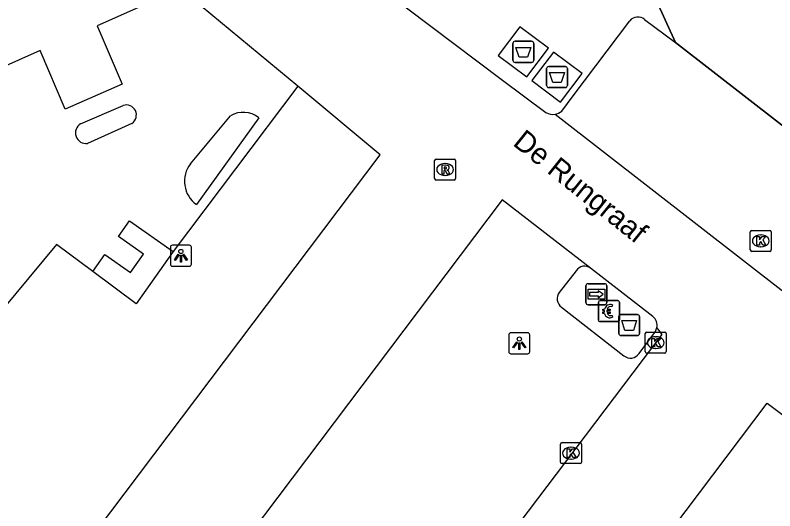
# Model space of a CAD drawing. Extents: x 160664 to 161506, y 382245 to 383288.
# Drawn here: x 161006.23 to 161042.33, y 382872.87 to 382896.43 of the extents above; entities that cross this region are included whole.
import ezdxf

# ---------------------------------------------------------------- set-up
doc = ezdxf.new("R2010")
doc.units = 0
for name, color, linetype in [('IMGEO_Afval_apart_plaats', 7, 'Continuous'), ('IMGEO_Afvalbak', 7, 'Continuous'), ('IMGEO_Betaalautomaat', 7, 'Continuous'), ('IMGEO_Kolk', 7, 'Continuous'), ('IMGEO_Lichtpunt', 7, 'Continuous'), ('IMGEO_Muur', 7, 'Continuous'), ('IMGEO_Openbare_ruimte_label', 7, 'Continuous'), ('IMGEO_Pand', 7, 'Continuous'), ('IMGEO_Parkeervlak_open', 7, 'Continuous'), ('IMGEO_Rijbaan_lokaal_open', 7, 'Continuous'), ('IMGEO_Rioolput', 7, 'Continuous'), ('IMGEO_Voetpad_gesloten', 7, 'Continuous'), ('IMGEO_Voetpad_open', 7, 'Continuous'), ('IMGEO_Wegwijzer', 7, 'Continuous')]:
    doc.layers.add(name, color=color, linetype=linetype)

msp = doc.modelspace()

# ---------------------------------------------------------------- linework, layer by layer
at = {"layer": 'IMGEO_Afval_apart_plaats'}
for p, q in [((161029.884, 382894.283), (161029.884, 382895.083)), ((161029.884, 382895.083), (161029.884, 382894.283)), ((161029.984, 382895.183), (161030.774, 382895.183)), ((161030.774, 382895.183), (161029.984, 382895.183)), ((161030.874, 382895.083), (161030.874, 382894.283)), ((161030.874, 382894.283), (161030.874, 382895.083)), ((161030.774, 382894.183), (161029.984, 382894.183)), ((161029.984, 382894.183), (161030.774, 382894.183)), ((161031.486, 382893.086), (161031.486, 382893.886)), ((161031.486, 382893.886), (161031.486, 382893.086)), ((161031.586, 382893.986), (161032.376, 382893.986)), ((161032.376, 382893.986), (161031.586, 382893.986)), ((161032.476, 382893.886), (161032.476, 382893.086)), ((161032.476, 382893.086), (161032.476, 382893.886)), ((161032.376, 382892.986), (161031.586, 382892.986)), ((161031.586, 382892.986), (161032.376, 382892.986))]:
    msp.add_line(p, q, dxfattribs=at)
for points in [[(161030.027, 382894.897), (161030.731, 382894.897), (161030.582, 382894.427), (161030.176, 382894.427), (161030.027, 382894.897)], [(161031.629, 382893.7), (161032.333, 382893.7), (161032.184, 382893.23), (161031.778, 382893.23), (161031.629, 382893.7)]]:
    msp.add_lwpolyline(points, dxfattribs=at)
for centre, start, end in [((161029.984, 382895.083), 90, 180), ((161029.984, 382895.083), 90, 180), ((161030.774, 382895.083), 0, 90), ((161030.774, 382895.083), 360, 90), ((161029.984, 382894.283), 180, 270), ((161029.984, 382894.283), 180, 270), ((161030.774, 382894.283), 270, 0), ((161030.774, 382894.283), 270, 0), ((161031.586, 382893.886), 90, 180), ((161031.586, 382893.886), 90, 180), ((161032.376, 382893.886), 0, 90), ((161032.376, 382893.886), 360, 90), ((161031.586, 382893.086), 180, 270), ((161031.586, 382893.086), 180, 270), ((161032.376, 382893.086), 270, 0), ((161032.376, 382893.086), 270, 0)]:
    msp.add_arc(centre, 0.1, start, end, dxfattribs=at)
at = {"layer": 'IMGEO_Afvalbak'}
for p, q in [((161034.915, 382881.298), (161034.915, 382882.098)), ((161034.915, 382882.098), (161034.915, 382881.298)), ((161035.015, 382882.198), (161035.805, 382882.198)), ((161035.805, 382882.198), (161035.015, 382882.198)), ((161035.905, 382882.098), (161035.905, 382881.298)), ((161035.905, 382881.298), (161035.905, 382882.098)), ((161035.805, 382881.198), (161035.015, 382881.198)), ((161035.015, 382881.198), (161035.805, 382881.198))]:
    msp.add_line(p, q, dxfattribs=at)
msp.add_lwpolyline([(161035.058, 382881.912), (161035.762, 382881.912), (161035.613, 382881.442), (161035.207, 382881.442), (161035.058, 382881.912)], dxfattribs=at)
for centre, start, end in [((161035.015, 382882.098), 90, 180), ((161035.015, 382882.098), 90, 180), ((161035.805, 382882.098), 0, 90), ((161035.805, 382882.098), 360, 90), ((161035.015, 382881.298), 180, 270), ((161035.015, 382881.298), 180, 270), ((161035.805, 382881.298), 270, 0), ((161035.805, 382881.298), 270, 0)]:
    msp.add_arc(centre, 0.1, start, end, dxfattribs=at)
at = {"layer": 'IMGEO_Betaalautomaat'}
for p, q in [((161033.948, 382881.936), (161033.948, 382882.777)), ((161033.948, 382882.777), (161033.948, 382881.936)), ((161034.023, 382882.86), (161034.864, 382882.86)), ((161034.864, 382882.86), (161034.023, 382882.86)), ((161034.947, 382882.786), (161034.947, 382881.945)), ((161034.947, 382881.945), (161034.947, 382882.786)), ((161034.231, 382882.324), (161034.231, 382882.392)), ((161034.352, 382882.392), (161034.352, 382882.324)), ((161034.61, 382882.665), (161034.593, 382882.565)), ((161034.597, 382882.159), (161034.619, 382882.072)), ((161034.873, 382881.861), (161034.032, 382881.861)), ((161034.032, 382881.861), (161034.873, 382881.861))]:
    msp.add_line(p, q, dxfattribs=at)
for points in [[(161034.231, 382882.392), (161034.162, 382882.392), (161034.162, 382882.461), (161034.241, 382882.461)], [(161034.363, 382882.461), (161034.51, 382882.461), (161034.51, 382882.392), (161034.352, 382882.392)], [(161034.236, 382882.255), (161034.162, 382882.255), (161034.162, 382882.324), (161034.231, 382882.324)], [(161034.352, 382882.324), (161034.51, 382882.324), (161034.51, 382882.255), (161034.366, 382882.255)]]:
    msp.add_lwpolyline(points, dxfattribs=at)
for centre, radius, start, end in [((161034.026, 382882.783), 0.0779, 92.4484, 184.2845), ((161034.026, 382882.783), 0.0779, 92.4484, 184.2845), ((161034.87, 382882.783), 0.0779, 2.4484, 94.2845), ((161034.87, 382882.783), 0.0779, 2.4484, 94.2845), ((161034.524, 382882.385), 0.293, 73.014, 165.0139), ((161034.53, 382882.398), 0.179, 69.3236, 159.5683), ((161034.497, 382882.31), 0.267, 191.8096, 297.0389), ((161034.53, 382882.325), 0.179, 202.7625, 291.8693), ((161034.026, 382881.939), 0.0779, 182.4484, 274.2845), ((161034.026, 382881.939), 0.0779, 182.4484, 274.2845), ((161034.87, 382881.939), 0.0779, 272.4484, 4.2845), ((161034.87, 382881.939), 0.0779, 272.4484, 4.2845)]:
    msp.add_arc(centre, radius, start, end, dxfattribs=at)
at = {"layer": 'IMGEO_Kolk'}
for p, q in [((161041.162, 382885.274), (161041.162, 382886.126)), ((161041.237, 382886.2), (161042.089, 382886.2)), ((161041.65, 382885.98), (161041.675, 382885.98)), ((161042.163, 382886.126), (161042.163, 382885.274)), ((161041.673, 382885.42), (161041.648, 382885.42)), ((161042.089, 382885.2), (161041.237, 382885.2)), ((161036.173, 382880.438), (161036.173, 382881.29)), ((161036.248, 382881.364), (161037.1, 382881.364)), ((161037.174, 382881.29), (161037.174, 382880.438)), ((161036.661, 382881.144), (161036.686, 382881.144)), ((161036.684, 382880.584), (161036.659, 382880.584)), ((161037.1, 382880.364), (161036.248, 382880.364)), ((161032.144, 382875.186), (161032.144, 382876.038)), ((161032.219, 382876.112), (161033.071, 382876.112)), ((161032.632, 382875.892), (161032.657, 382875.892)), ((161033.145, 382876.038), (161033.145, 382875.186)), ((161032.655, 382875.332), (161032.63, 382875.332)), ((161033.071, 382875.112), (161032.219, 382875.112))]:
    msp.add_line(p, q, dxfattribs=at)
for points in [[(161041.162, 382885.274), (161041.162, 382886.126)], [(161041.237, 382886.2), (161042.089, 382886.2)], [(161042.163, 382886.126), (161042.163, 382885.274)], [(161041.483, 382885.9), (161041.606, 382885.9), (161041.606, 382885.749), (161041.736, 382885.9), (161041.9, 382885.9), (161041.754, 382885.749), (161041.907, 382885.5), (161041.755, 382885.5), (161041.67, 382885.664), (161041.606, 382885.597), (161041.606, 382885.5), (161041.483, 382885.5), (161041.483, 382885.9)], [(161042.089, 382885.2), (161041.237, 382885.2)], [(161036.173, 382880.438), (161036.173, 382881.29)], [(161036.248, 382881.364), (161037.1, 382881.364)], [(161037.174, 382881.29), (161037.174, 382880.438)], [(161036.494, 382881.064), (161036.617, 382881.064), (161036.617, 382880.913), (161036.747, 382881.064), (161036.911, 382881.064), (161036.765, 382880.913), (161036.918, 382880.664), (161036.766, 382880.664), (161036.681, 382880.828), (161036.617, 382880.761), (161036.617, 382880.664), (161036.494, 382880.664), (161036.494, 382881.064)], [(161037.1, 382880.364), (161036.248, 382880.364)], [(161032.144, 382875.186), (161032.144, 382876.038)], [(161032.219, 382876.112), (161033.071, 382876.112)], [(161033.145, 382876.038), (161033.145, 382875.186)], [(161032.465, 382875.812), (161032.588, 382875.812), (161032.588, 382875.661), (161032.718, 382875.812), (161032.882, 382875.812), (161032.736, 382875.661), (161032.889, 382875.412), (161032.737, 382875.412), (161032.652, 382875.576), (161032.588, 382875.509), (161032.588, 382875.412), (161032.465, 382875.412), (161032.465, 382875.812)], [(161033.071, 382875.112), (161032.219, 382875.112)]]:
    msp.add_lwpolyline(points, dxfattribs=at)
for centre, start, end in [((161041.239, 382886.124), 91.552, 178.448), ((161041.239, 382886.124), 91.552, 178.448), ((161042.087, 382886.124), 1.552, 88.448), ((161042.087, 382886.124), 1.552, 88.448), ((161041.239, 382885.276), 181.552, 268.448), ((161041.239, 382885.276), 181.552, 268.448), ((161042.087, 382885.276), 271.552, 358.448), ((161042.087, 382885.276), 271.552, 358.448), ((161036.25, 382881.288), 91.552, 178.448), ((161036.25, 382881.288), 91.552, 178.448), ((161037.098, 382881.288), 1.552, 88.448), ((161037.098, 382881.288), 1.552, 88.448), ((161036.25, 382880.44), 181.552, 268.448), ((161036.25, 382880.44), 181.552, 268.448), ((161037.098, 382880.44), 271.552, 358.448), ((161037.098, 382880.44), 271.552, 358.448), ((161032.221, 382876.036), 91.552, 178.448), ((161032.221, 382876.036), 91.552, 178.448), ((161033.069, 382876.036), 1.552, 88.448), ((161033.069, 382876.036), 1.552, 88.448), ((161032.221, 382875.188), 181.552, 268.448), ((161032.221, 382875.188), 181.552, 268.448), ((161033.069, 382875.188), 271.552, 358.448), ((161033.069, 382875.188), 271.552, 358.448)]:
    msp.add_arc(centre, 0.0765, start, end, dxfattribs=at)
for centre, major_axis, ratio, start_param, end_param in [((161041.649, 382885.7), (-0.387, 0.002), 0.722429, 4.712389, 7.853982), ((161041.674, 382885.7), (-0.39, 0.002), 0.717154, 1.570796, 4.712389), ((161036.66, 382880.864), (-0.387, 0.002), 0.722429, 4.712389, 7.853982), ((161036.685, 382880.864), (-0.39, 0.002), 0.717154, 1.570796, 4.712389), ((161032.631, 382875.612), (-0.387, 0.002), 0.722429, 4.712389, 7.853982), ((161032.656, 382875.612), (-0.39, 0.002), 0.717154, 1.570796, 4.712389)]:
    msp.add_ellipse(centre, major_axis=major_axis, ratio=ratio, start_param=start_param, end_param=end_param, dxfattribs=at)
at = {"layer": 'IMGEO_Lichtpunt'}
for p, q in [((161013.608, 382885.398), (161013.608, 382884.591)), ((161013.608, 382885.398), (161013.608, 382884.591)), ((161014.51, 382885.493), (161013.702, 382885.493)), ((161014.51, 382885.493), (161013.702, 382885.493)), ((161014.604, 382884.591), (161014.604, 382885.398)), ((161014.604, 382884.591), (161014.604, 382885.398)), ((161013.702, 382884.497), (161014.51, 382884.497)), ((161013.702, 382884.497), (161014.51, 382884.497)), ((161030.593, 382881.332), (161029.785, 382881.332)), ((161030.593, 382881.332), (161029.785, 382881.332)), ((161029.691, 382881.237), (161029.691, 382880.43)), ((161029.691, 382881.237), (161029.691, 382880.43)), ((161030.687, 382880.43), (161030.687, 382881.237)), ((161030.687, 382880.43), (161030.687, 382881.237)), ((161029.785, 382880.336), (161030.593, 382880.336)), ((161029.785, 382880.336), (161030.593, 382880.336))]:
    msp.add_line(p, q, dxfattribs=at)
for points in [[(161013.982, 382885.062), (161014.021, 382885.034), (161013.833, 382884.772), (161013.795, 382884.799), (161013.982, 382885.062)], [(161014.084, 382885.014), (161014.131, 382885.014), (161014.131, 382884.692), (161014.084, 382884.692), (161014.084, 382885.014)], [(161014.194, 382885.034), (161014.232, 382885.061), (161014.419, 382884.799), (161014.38, 382884.771), (161014.194, 382885.034)], [(161030.065, 382880.901), (161030.104, 382880.873), (161029.916, 382880.611), (161029.878, 382880.638), (161030.065, 382880.901)], [(161030.277, 382880.873), (161030.315, 382880.9), (161030.502, 382880.638), (161030.463, 382880.61), (161030.277, 382880.873)], [(161030.167, 382880.853), (161030.214, 382880.853), (161030.214, 382880.531), (161030.167, 382880.531), (161030.167, 382880.853)]]:
    msp.add_lwpolyline(points, dxfattribs=at)
for centre in [(161014.107, 382885.196), (161030.19, 382881.035)]:
    msp.add_circle(centre, 0.0994, dxfattribs=at)
for centre, start, end in [((161013.702, 382885.398), 90, 180), ((161013.702, 382885.398), 90, 180), ((161014.51, 382885.398), 0, 90), ((161014.51, 382885.398), 0, 90), ((161013.702, 382884.591), 180, 270), ((161013.702, 382884.591), 180, 270), ((161014.51, 382884.591), 270, 0), ((161014.51, 382884.591), 270, 360), ((161029.785, 382881.237), 90, 180), ((161029.785, 382881.237), 90, 180), ((161030.593, 382881.237), 0, 90), ((161030.593, 382881.237), 0, 90), ((161029.785, 382880.43), 180, 270), ((161029.785, 382880.43), 180, 270), ((161030.593, 382880.43), 270, 0), ((161030.593, 382880.43), 270, 360)]:
    msp.add_arc(centre, 0.0946, start, end, dxfattribs=at)
at = {"layer": 'IMGEO_Muur'}
for points in [[(161037.616, 382895.122), (161035.229, 382900.358)], [(161055.707, 382881.074), (161037.616, 382895.122)]]:
    msp.add_lwpolyline(points, dxfattribs=at)
at = {"layer": 'IMGEO_Pand'}
msp.add_lwpolyline([(161014.607, 382897.256), (161014.294, 382897.128), (161014.052, 382897.682), (161010.131, 382895.912), (161011.314, 382893.149), (161008.614, 382891.962), (161007.416, 382894.745), (161001.969, 382892.326)], dxfattribs=at)
at = {"layer": 'IMGEO_Parkeervlak_open'}
for points in [[(161037.616, 382895.122), (161055.707, 382881.074)], [(161013.737, 382885.191), (161011.983, 382882.707), (161009.918, 382884.242)], [(161032.897, 382884.273), (161032.088, 382883.243)], [(161032.196, 382882.556), (161035.156, 382880.239)], [(161035.877, 382880.352), (161036.656, 382881.396), (161036.728, 382881.578)]]:
    msp.add_lwpolyline(points, dxfattribs=at)
for centre, radius, start, end in [((161033.296, 382884.035), 0.465, 52.7846, 149.1864), ((161032.463, 382882.95), 0.476, 142.0313, 235.8369), ((161035.467, 382880.614), 0.487, 230.3779, 327.4368)]:
    msp.add_arc(centre, radius, start, end, dxfattribs=at)
at = {"layer": 'IMGEO_Rijbaan_lokaal_open'}
for points in [[(161021.072, 382900.069), (161021.429, 382899.354), (161029.397, 382893.332), (161031.451, 382891.801)], [(161019.667, 382893.047), (161014.607, 382897.256)], [(161009.04, 382847.522), (161000, 382856.514), (160999.119, 382857.39), (161000, 382858.557), (161023.576, 382889.795), (161019.667, 382893.047)], [(161019.667, 382893.047), (161013.737, 382885.191)], [(161009.339, 382891.266), (161011.367, 382892.137)], [(161014.562, 382889.368), (161016.46, 382891.642)], [(161017.809, 382891.547), (161014.848, 382887.425)], [(161031.89, 382891.715), (161051.844, 382876.215), (161052.657, 382877.184), (161052.932, 382876.971), (161053.162, 382877.241)], [(161011.779, 382891.285), (161009.674, 382890.329)], [(161033.577, 382884.405), (161029.375, 382887.651), (161006.741, 382857.643), (161014.674, 382851.774), (161036.973, 382881.256), (161036.728, 382881.578)], [(161009.918, 382884.242), (161010.488, 382885.049), (161011.711, 382884.193), (161012.331, 382885.071), (161011.148, 382885.907), (161011.672, 382886.65), (161013.737, 382885.191)], [(161009.918, 382884.242), (161008.193, 382885.524), (160999.832, 382875.47), (160993.888, 382867.215), (160990.918, 382863.091), (160990.417, 382861.086), (160992.626, 382856.489), (161001.149, 382847.95), (161005.762, 382843.842)], [(161036.539, 382882.101), (161033.577, 382884.405)], [(161041.959, 382877.99), (161050.071, 382871.893), (161026.197, 382840.33), (161018.147, 382846.412), (161041.959, 382877.99)]]:
    msp.add_lwpolyline(points, dxfattribs=at)
for centre, radius, start, end in [((161011.513, 382891.682), 0.478, 303.8506, 107.7633), ((161017.066, 382890.627), 1.183, 51.101, 120.8425), ((161031.785, 382892.341), 0.635, 238.2925, 279.5398), ((161009.604, 382890.833), 0.508, 121.4862, 277.8601), ((161015.642, 382888.534), 1.364, 142.3441, 234.403), ((161036.199, 382881.682), 0.539, 348.8379, 50.8995)]:
    msp.add_arc(centre, radius, start, end, dxfattribs=at)
at = {"layer": 'IMGEO_Rioolput'}
for p, q in [((161026.237, 382889.59), (161027.089, 382889.59)), ((161026.162, 382888.664), (161026.162, 382889.516)), ((161026.65, 382889.37), (161026.675, 382889.37)), ((161027.163, 382889.516), (161027.163, 382888.664)), ((161027.089, 382888.59), (161026.237, 382888.59)), ((161026.673, 382888.81), (161026.648, 382888.81))]:
    msp.add_line(p, q, dxfattribs=at)
for points in [[(161026.237, 382889.59), (161027.089, 382889.59)], [(161026.162, 382888.664), (161026.162, 382889.516)], [(161026.751, 382889.288), (161026.499, 382889.29), (161026.499, 382888.89)], [(161026.677, 382889.209), (161026.623, 382889.209), (161026.623, 382889.128)], [(161027.163, 382889.516), (161027.163, 382888.664)], [(161026.499, 382888.89), (161026.623, 382888.89), (161026.623, 382889.052), (161026.634, 382889.052)], [(161026.623, 382889.128), (161026.675, 382889.128)], [(161026.681, 382889.023), (161026.752, 382888.89), (161026.892, 382888.89), (161026.827, 382889.016)], [(161027.089, 382888.59), (161026.237, 382888.59)]]:
    msp.add_lwpolyline(points, dxfattribs=at)
for centre, radius, start, end in [((161026.239, 382889.514), 0.0765, 91.552, 178.448), ((161026.239, 382889.514), 0.0765, 91.552, 178.448), ((161027.087, 382889.514), 0.0765, 1.552, 88.448), ((161027.087, 382889.514), 0.0765, 1.552, 88.448), ((161026.683, 382889.113), 0.0964, 77.0061, 93.1865), ((161026.697, 382889.17), 0.0378, 276.6634, 79.6772), ((161026.75, 382889.178), 0.109, 350.3612, 89.416), ((161026.633, 382888.999), 0.0533, 26.0293, 88.6989), ((161026.659, 382889.317), 0.19, 274.7715, 282.9687), ((161026.748, 382889.178), 0.112, 277.5842, 350.9817), ((161026.732, 382888.963), 0.108, 29.5134, 73.7905), ((161026.239, 382888.666), 0.0765, 181.552, 268.448), ((161026.239, 382888.666), 0.0765, 181.552, 268.448), ((161027.087, 382888.666), 0.0765, 271.552, 358.448), ((161027.087, 382888.666), 0.0765, 271.552, 358.448)]:
    msp.add_arc(centre, radius, start, end, dxfattribs=at)
for centre, major_axis, ratio, start_param, end_param in [((161026.649, 382889.09), (-0.387, 0.002), 0.722429, 4.712389, 7.853982), ((161026.674, 382889.09), (-0.39, 0.002), 0.717154, 1.570796, 4.712389)]:
    msp.add_ellipse(centre, major_axis=major_axis, ratio=ratio, start_param=start_param, end_param=end_param, dxfattribs=at)
at = {"layer": 'IMGEO_Voetpad_gesloten'}
for points in [[(161031.569, 382894.855), (161030.207, 382895.873), (161029.189, 382894.511), (161030.551, 382893.493), (161031.569, 382894.855)], [(161033.171, 382893.658), (161031.809, 382894.675), (161030.791, 382893.314), (161032.153, 382892.296), (161033.171, 382893.658)]]:
    msp.add_lwpolyline(points, dxfattribs=at)
at = {"layer": 'IMGEO_Voetpad_open'}
for points in [[(161035.229, 382900.358), (161037.616, 382895.122)], [(161032.206, 382891.868), (161032.752, 382892.592), (161035.441, 382896.16)], [(161036.145, 382896.226), (161037.616, 382895.122)]]:
    msp.add_lwpolyline(points, dxfattribs=at)
for centre, radius, start, end in [((161035.826, 382895.842), 0.499, 50.2931, 140.4186), ((161031.785, 382892.334), 0.628, 279.5962, 312.0742)]:
    msp.add_arc(centre, radius, start, end, dxfattribs=at)
at = {"layer": 'IMGEO_Wegwijzer'}
for p, q in [((161033.356, 382882.765), (161033.356, 382883.565)), ((161033.356, 382883.565), (161033.356, 382882.765)), ((161033.456, 382883.665), (161034.246, 382883.665)), ((161034.246, 382883.665), (161033.456, 382883.665)), ((161034.346, 382883.565), (161034.346, 382882.765)), ((161034.346, 382882.765), (161034.346, 382883.565)), ((161034.246, 382882.665), (161033.456, 382882.665)), ((161033.456, 382882.665), (161034.246, 382882.665))]:
    msp.add_line(p, q, dxfattribs=at)
for points in [[(161033.457, 382883.397), (161034.245, 382883.397), (161034.245, 382882.933), (161033.457, 382882.933), (161033.457, 382883.397)], [(161033.522, 382883.249), (161033.522, 382883.165), (161033.522, 382883.081), (161033.933, 382883.081), (161033.933, 382882.998), (161034.18, 382883.165), (161033.933, 382883.332), (161033.933, 382883.249), (161033.522, 382883.249)]]:
    msp.add_lwpolyline(points, dxfattribs=at)
for centre, start, end in [((161033.456, 382883.565), 90, 180), ((161033.456, 382883.565), 90, 180), ((161034.246, 382883.565), 0, 90), ((161034.246, 382883.565), 360, 90), ((161033.456, 382882.765), 180, 270), ((161033.456, 382882.765), 180, 270), ((161034.246, 382882.765), 270, 0), ((161034.246, 382882.765), 270, 0)]:
    msp.add_arc(centre, 0.1, start, end, dxfattribs=at)

# ---------------------------------------------------------------- texts
at = {"layer": 'IMGEO_Openbare_ruimte_label'}
msp.add_text('De Rungraaf', height=1, rotation=321.2507, dxfattribs=at).set_placement((161029.833, 382890.278))

doc.saveas('drawing.dxf')
